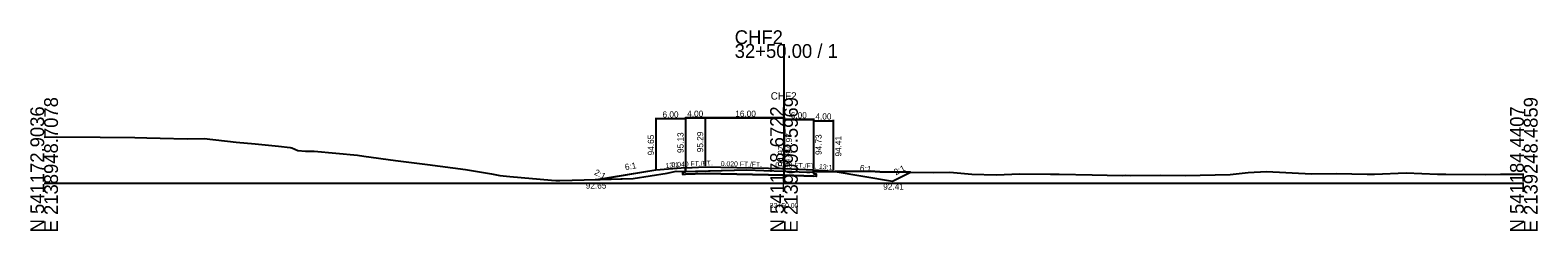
# Model space of a CAD drawing. Extents: x -12831 to 2303, y -10 to 39065.
# Drawn here: x 997.2 to 1302.8, y 4990.3 to 5031.1 of the extents above; entities that cross this region are included whole.
import ezdxf

# ---------------------------------------------------------------- set-up
doc = ezdxf.new("R2010")
doc.units = 0
for name, color, linetype in [('Level 5', 7, 'Continuous'), ('Level 53', 7, 'Continuous'), ('Level 54', 7, 'Continuous'), ('Level 55', 7, 'Continuous'), ('Level 7', 7, 'Continuous'), ('RD_GPK_XS_Cell', 7, 'Continuous'), ('RD_XS_EwShp', 7, 'Continuous'), ('RD_XS_ExGround', 7, 'Continuous'), ('RD_XS_Pave', 7, 'Continuous'), ('RD_XS_TX_Baseline', 7, 'Continuous'), ('RD_XS_TX_Ditch', 7, 'Continuous'), ('RD_XS_TX_Elev_EX', 7, 'Continuous'), ('RD_XS_TX_Elev_PR', 7, 'Continuous'), ('RD_XS_TX_Station', 7, 'Continuous')]:
    doc.layers.add(name, color=color, linetype=linetype)

msp = doc.modelspace()

# ---------------------------------------------------------------- linework, layer by layer
at = {"layer": 'Level 5'}
for p, q in [((1130, 5002.3), (1129.5, 5002.28)), ((1129.5, 5002.28), (1129.5, 5001.78)), ((1129.5, 5001.78), (1130, 5001.8)), ((1130, 5003.13), (1130, 5002.3)), ((1134, 5001.96), (1130, 5001.8)), ((1134, 5001.96), (1130, 5001.8)), ((1130, 5001.8), (1134, 5001.96)), ((1150, 5001.64), (1134, 5001.96)), ((1150, 5001.64), (1134, 5001.96)), ((1134, 5001.96), (1150, 5001.64)), ((1134, 5001.96), (1150, 5001.64)), ((1156, 5001.4), (1150, 5001.64)), ((1150, 5001.64), (1156, 5001.4)), ((1150, 5001.64), (1156, 5001.4)), ((1156, 5002.73), (1156, 5001.9)), ((1156, 5001.9), (1156.5, 5001.88)), ((1156.5, 5001.38), (1156, 5001.4)), ((1156.5, 5001.88), (1156.5, 5001.38))]:
    msp.add_line(p, q, dxfattribs=at)
at = {"layer": 'Level 54'}
for p, q in [((1124, 5013.28), (1124, 5002.85)), ((1130, 5013.44), (1130, 5003.33)), ((1130, 5013.44), (1130, 5003.33)), ((1130, 5013.44), (1130, 5003.33)), ((1130, 5013.28), (1130, 5003.33)), ((1130, 5013.24), (1134, 5013.24)), ((1130, 5013.24), (1134, 5013.24)), ((1134, 5013.24), (1130, 5013.24)), ((1134, 5013.44), (1134, 5003.49)), ((1134, 5013.44), (1134, 5003.49)), ((1134, 5013.44), (1134, 5003.49)), ((1134, 5013.44), (1134, 5003.49)), ((1134, 5013.44), (1134, 5003.49)), ((1134, 5013.44), (1134, 5003.49)), ((1134, 5013.44), (1134, 5003.49)), ((1134, 5013.24), (1150, 5013.24)), ((1134, 5013.24), (1150, 5013.24)), ((1150, 5013.24), (1134, 5013.24)), ((1150, 5013.24), (1134, 5013.24)), ((1150, 5013.44), (1150, 5003.17)), ((1150, 5013.44), (1150, 5003.17)), ((1150, 5013.44), (1150, 5003.17)), ((1150, 5013.44), (1150, 5003.17)), ((1130, 5013.08), (1124, 5013.08)), ((1150, 5013.12), (1150, 5003.17)), ((1150, 5013.12), (1150, 5003.17)), ((1150, 5013.12), (1150, 5003.17)), ((1150, 5012.92), (1156, 5012.92)), ((1156, 5012.92), (1150, 5012.92)), ((1156, 5012.92), (1150, 5012.92)), ((1156, 5013.12), (1156, 5002.93)), ((1156, 5013.12), (1156, 5002.93)), ((1156, 5013.12), (1156, 5002.93)), ((1156, 5012.88), (1156, 5002.93)), ((1156, 5012.68), (1160, 5012.68)), ((1160, 5012.88), (1160, 5002.61))]:
    msp.add_line(p, q, dxfattribs=at)
at = {"layer": 'Level 7'}
for p, q in [((1124, 5002.65), (1112, 5000.65)), ((1130, 5003.13), (1124, 5002.65)), ((1156, 5002.73), (1160, 5002.41)), ((1160, 5002.41), (1172, 5000.41)), ((1172, 5000.41), (1175.67, 5002.24)), ((1112, 5000.65), (1111.8, 5000.75))]:
    msp.add_line(p, q, dxfattribs=at)
at = {"layer": 'RD_GPK_XS_Cell'}
for p, q in [((1150, 5000), (1150, 5028.25)), ((1000, 5000), (1150, 5000)), ((1150, 5000), (1300, 5000))]:
    msp.add_line(p, q, dxfattribs=at)
at = {"layer": 'RD_XS_EwShp'}
for points in [[(1126.34, 5002.05), (1128.16, 5002.41), (1129.52, 5002.37), (1130, 5002.38), (1130, 5003.13), (1124, 5002.65), (1112.74, 5000.77), (1119.4, 5000.94)], [(1156, 5001.9), (1156.5, 5001.88), (1156.5, 5001.38), (1156, 5001.4), (1150, 5001.64), (1134, 5001.96), (1130, 5001.8), (1129.5, 5001.78), (1129.5, 5002.28), (1130, 5002.3), (1130, 5002.38), (1142.44, 5002.68), (1145.94, 5002.56), (1150, 5002.42), (1154.66, 5002.27), (1155.24, 5002.27), (1155.93, 5002.3), (1156, 5002.3)], [(1160, 5002.41), (1160.37, 5002.35), (1156, 5002.3), (1156, 5002.73)], [(1160.37, 5002.35), (1172, 5000.41), (1175.67, 5002.24), (1169.45, 5002.33), (1167.44, 5002.42)], [(1111.8, 5000.75), (1112.74, 5000.77), (1112, 5000.65)]]:
    msp.add_lwpolyline(points, close=True, dxfattribs=at)
at = {"layer": 'RD_XS_ExGround'}
for p, q in [((1000, 5009.36), (1002.47, 5009.42)), ((1002.47, 5009.42), (1011.37, 5009.33)), ((1011.37, 5009.33), (1018.41, 5009.26)), ((1018.41, 5009.26), (1020.83, 5009.19)), ((1020.83, 5009.19), (1023.54, 5009.13)), ((1023.54, 5009.13), (1028.99, 5009)), ((1028.99, 5009), (1032.44, 5009.06)), ((1032.44, 5009.06), (1038.96, 5008.34)), ((1038.96, 5008.34), (1042.79, 5007.99)), ((1042.79, 5007.99), (1047.49, 5007.51)), ((1047.49, 5007.51), (1049.88, 5007.28)), ((1049.88, 5007.28), (1050.19, 5007.19)), ((1050.19, 5007.19), (1051.46, 5006.62)), ((1051.46, 5006.62), (1052.98, 5006.53)), ((1052.98, 5006.53), (1053.29, 5006.49)), ((1053.29, 5006.49), (1054.71, 5006.48)), ((1054.71, 5006.48), (1063.55, 5005.67)), ((1063.55, 5005.67), (1064.81, 5005.52)), ((1064.81, 5005.52), (1071.21, 5004.64)), ((1071.21, 5004.64), (1077.75, 5003.77)), ((1077.75, 5003.77), (1085.4, 5002.81)), ((1085.4, 5002.81), (1090.69, 5001.89)), ((1090.69, 5001.89), (1092.37, 5001.58)), ((1092.37, 5001.58), (1094.43, 5001.36)), ((1094.43, 5001.36), (1102.83, 5000.6)), ((1119.4, 5000.94), (1126.34, 5002.05)), ((1126.34, 5002.05), (1128.16, 5002.41)), ((1128.16, 5002.41), (1129.52, 5002.37)), ((1129.52, 5002.37), (1142.44, 5002.68)), ((1142.44, 5002.68), (1145.94, 5002.56)), ((1145.94, 5002.56), (1150, 5002.42)), ((1150, 5002.42), (1154.66, 5002.27)), ((1154.66, 5002.27), (1155.24, 5002.27)), ((1155.24, 5002.27), (1155.93, 5002.3)), ((1155.93, 5002.3), (1167.44, 5002.42)), ((1167.44, 5002.42), (1169.45, 5002.33)), ((1169.45, 5002.33), (1180.23, 5002.18)), ((1180.23, 5002.18), (1183.61, 5002.25)), ((1183.61, 5002.25), (1188.05, 5001.85)), ((1188.05, 5001.85), (1193.01, 5001.68)), ((1193.01, 5001.68), (1197.84, 5001.93)), ((1197.84, 5001.93), (1204.03, 5001.85)), ((1204.03, 5001.85), (1205.79, 5001.85)), ((1205.79, 5001.85), (1212.45, 5001.72)), ((1212.45, 5001.72), (1218.58, 5001.59)), ((1218.58, 5001.59), (1219.3, 5001.6)), ((1219.3, 5001.6), (1220.18, 5001.57)), ((1220.18, 5001.57), (1226.43, 5001.65)), ((1226.43, 5001.65), (1231.36, 5001.53)), ((1231.36, 5001.53), (1240.48, 5001.73)), ((1240.48, 5001.73), (1244.14, 5002.15)), ((1244.14, 5002.15), (1247.81, 5002.37)), ((1247.81, 5002.37), (1256.93, 5001.9)), ((1256.93, 5001.9), (1261.99, 5001.96)), ((1261.99, 5001.96), (1268.24, 5001.84)), ((1268.24, 5001.84), (1269.71, 5001.86)), ((1269.71, 5001.86), (1276.17, 5002.07)), ((1276.17, 5002.07), (1282.49, 5001.86)), ((1282.49, 5001.86), (1283.2, 5001.84)), ((1283.2, 5001.84), (1284.17, 5001.83)), ((1284.17, 5001.83), (1292.2, 5001.77)), ((1292.2, 5001.77), (1295.28, 5001.86)), ((1295.28, 5001.86), (1300, 5001.85)), ((1102.83, 5000.6), (1103.73, 5000.57)), ((1103.73, 5000.57), (1104.58, 5000.57)), ((1104.58, 5000.57), (1119.4, 5000.94))]:
    msp.add_line(p, q, dxfattribs=at)
at = {"layer": 'RD_XS_Pave'}
for p, q in [((1130, 5003.13), (1134, 5003.29)), ((1134, 5003.29), (1150, 5002.97)), ((1150, 5002.97), (1156, 5002.73))]:
    msp.add_line(p, q, dxfattribs=at)

# ---------------------------------------------------------------- texts
at = {"layer": 'Level 53'}
for s, rotation, p in [('95.13', 90, (1129.63, 5006.13)), ('95.29', 90, (1133.62, 5006.29)), ('95.29', 90, (1133.62, 5006.29)), ('94.65', 90, (1123.63, 5005.65)), ('94.97', 90, (1151.63, 5005.97)), ('94.97', 90, (1151.63, 5005.97)), ('94.73', 90, (1157.63, 5005.73)), ('94.41', 90, (1161.63, 5005.41)), ('6:1', 9.4623, (1117.84, 5002.64)), ('6:1', 350.5377, (1165.3, 5002.54))]:
    msp.add_text(s, height=1.25, rotation=rotation, dxfattribs=at).set_placement(p)
msp.add_text('92.41', height=1.25, dxfattribs=at).set_placement((1170.11, 4998.66))
at = {"layer": 'Level 54'}
for s, p in [('6.00', (1125.37, 5013.33)), ('4.00', (1130.37, 5013.49)), ('4.00', (1130.37, 5013.49)), ('4.00', (1130.37, 5013.49)), ('16.00', (1140.12, 5013.49)), ('16.00', (1140.12, 5013.49)), ('16.00', (1140.12, 5013.49)), ('16.00', (1140.12, 5013.49)), ('6.00', (1151.37, 5013.17)), ('6.00', (1151.37, 5013.17)), ('6.00', (1151.37, 5013.17)), ('4.00', (1156.37, 5012.93))]:
    msp.add_text(s, height=1.25, dxfattribs=at).set_placement(p)
at = {"layer": 'Level 55'}
for s, height, rotation, p in [('13:1', 1, 4.5739, (1126.03, 5003.06)), ('0.040 FT./FT.', 1, 2.2906, (1127.22, 5003.27)), ('0.040 FT./FT.', 1, 2.2906, (1127.22, 5003.27)), ('0.040 FT./FT.', 1, 2.2906, (1127.22, 5003.27)), ('0.020 FT./FT.', 1, 358.8542, (1137.18, 5003.48)), ('0.020 FT./FT.', 1, 358.8542, (1137.18, 5003.48)), ('0.020 FT./FT.', 1, 358.8542, (1137.18, 5003.48)), ('0.020 FT./FT.', 1, 358.8542, (1137.18, 5003.48)), ('0.040 FT./FT.', 1, 357.7094, (1148.24, 5003.29)), ('0.040 FT./FT.', 1, 357.7094, (1148.24, 5003.29)), ('0.040 FT./FT.', 1, 357.7094, (1148.24, 5003.29)), ('2:1', 1.25, 333.4349, (1111.4, 5001.79)), ('13:1', 1, 355.4261, (1157.07, 5002.9)), ('2:1', 1.25, 26.5651, (1172.66, 5001.58))]:
    msp.add_text(s, height=height, rotation=rotation, dxfattribs=at).set_placement(p)
at = {"layer": 'RD_GPK_XS_Cell'}
for s, p in [('CHF2', (1140, 5028.25)), ('32+50.00 / 1', (1140, 5025.45))]:
    msp.add_text(s, height=2.8, dxfattribs=at).set_placement(p)
for s, p in [('E 2138948.7078', (1002.8, 4990)), ('E 2139098.5969', (1152.8, 4990)), ('E 2139248.4859', (1302.8, 4990)), ('N 541172.9036', (1000, 4990)), ('N 541178.6722', (1150, 4990)), ('N 541184.4407', (1300, 4990))]:
    msp.add_text(s, height=2.8, rotation=90, dxfattribs=at).set_placement(p)
at = {"layer": 'RD_XS_TX_Baseline'}
msp.add_text('CHF2', height=1.5, dxfattribs=at).set_placement((1147.31, 5016.97))
at = {"layer": 'RD_XS_TX_Ditch'}
msp.add_text('92.65', height=1.25, dxfattribs=at).set_placement((1109.81, 4998.9))
at = {"layer": 'RD_XS_TX_Elev_EX'}
msp.add_text('94.42', height=1, rotation=90, dxfattribs=at).set_placement((1151.25, 5003.42))
at = {"layer": 'RD_XS_TX_Elev_PR'}
msp.add_text(' 94.97', height=1.25, rotation=90, dxfattribs=at).set_placement((1150, 5002.97))
at = {"layer": 'RD_XS_TX_Station'}
msp.add_text('32+50.00', height=1, dxfattribs=at).set_placement((1147.11, 4994.97))

doc.saveas('drawing.dxf')
